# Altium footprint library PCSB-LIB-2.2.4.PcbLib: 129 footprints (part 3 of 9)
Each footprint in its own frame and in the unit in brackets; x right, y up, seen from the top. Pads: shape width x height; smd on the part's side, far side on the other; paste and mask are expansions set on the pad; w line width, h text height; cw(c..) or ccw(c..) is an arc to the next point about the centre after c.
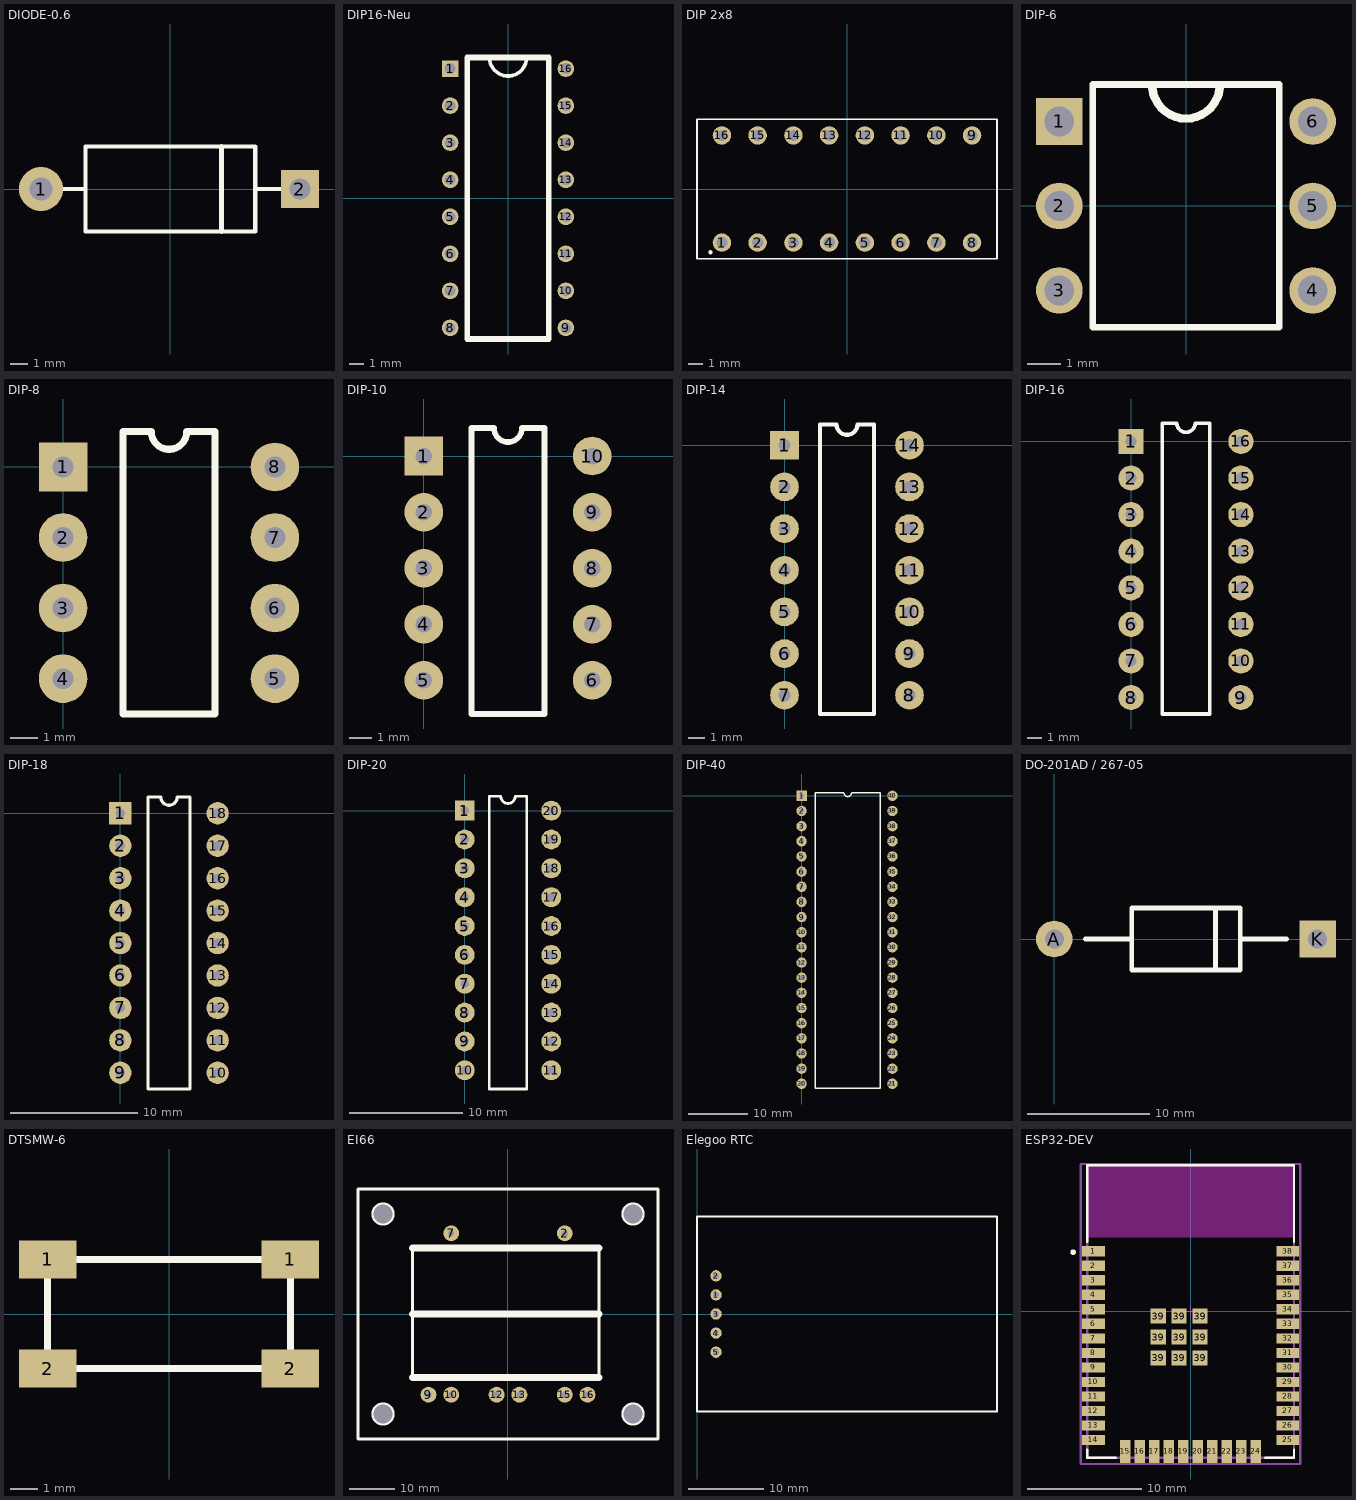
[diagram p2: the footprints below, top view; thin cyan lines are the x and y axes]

## DIODE-0.6 [mm]
pads (2):
  round 2.6 hole 1.35: 1(-7.62,0)
  rect 2.25x2.25 hole 1.25: 2(7.62,0)
Top Overlay:
  lines w0.254: -7,0 -5,0 ; -5,-2.5 -5,2.5 5,2.5 5,-2.5 -4.89,-2.5 ; 5,0 7.016,0
  lines w0.3: 3,-2.5 3,2.5

## DIP16-Neu [mm]
pads (16):
  rect 1.14x1.14 hole 0.74: 1(-3.97,8.89)
  round 1.14 hole 0.74: 2(-3.97,6.35) 3(-3.97,3.81) 4(-3.97,1.27) 5(-3.97,-1.27) 6(-3.97,-3.81) 7(-3.97,-6.35) 8(-3.97,-8.89) 9(3.97,-8.89) 10(3.97,-6.35) 11(3.97,-3.81) 12(3.97,-1.27) 13(3.97,1.27) 14(3.97,3.81) 15(3.97,6.35) 16(3.97,8.89)
Top Overlay:
  lines w0.254: -1.253,9.443 ccw(c0,9.653) 1.27,9.652
  lines w0.4: -2.794,-9.653 -2.794,9.653 2.794,9.653 2.794,-9.653 -2.794,-9.653

## DIP 2x8 [mm]
pads (16):
  round 1.308 hole 0.8: 1(-8.89,-3.81) 2(-6.35,-3.81) 3(-3.81,-3.81) 4(-1.27,-3.81) 5(1.27,-3.81) 6(3.81,-3.81) 7(6.35,-3.81) 8(8.89,-3.81) 9(8.89,3.81) 10(6.35,3.81) 11(3.81,3.81) 12(1.27,3.81) 13(-1.27,3.81) 14(-3.81,3.81) 15(-6.35,3.81) 16(-8.89,3.81)
Top Overlay:
  circle w0.2: c-9.7,-4.5 r0.05
  lines w0.127: -10.66,-4.95 -10.66,4.95 10.66,4.95 10.66,-4.95 -10.66,-4.95

## DIP-6 [mm]
pads (6):
  rect 1.4x1.4 hole 0.9: 1(-3.81,2.54)
  round 1.4 hole 0.9: 2(-3.81,0) 3(-3.81,-2.54) 4(3.81,-2.54) 5(3.81,0) 6(3.81,2.54)
Top Overlay:
  lines w0.2: -2.8,-3.65 2.8,-3.65 2.8,3.65 1.4,3.65 -1.4,3.65 -2.8,3.65 -2.8,-3.65
  lines w0.254: -1.016,3.556 ccw(c0,3.65) 1.016,3.556

## DIP-8 [mm]
pads (8):
  rect 1.75x1.75 hole 0.75: 1(0,0)
  round 1.75 hole 0.75: 2(0,-2.54) 3(0,-5.08) 4(0,-7.62) 5(7.62,-7.62) 6(7.62,-5.08) 7(7.62,-2.54) 8(7.62,0)
Top Overlay:
  lines w0.254: 2.159,-8.89 5.461,-8.89 5.461,1.27 4.445,1.27 cw(c3.81,1.27) 3.175,1.27 2.159,1.27 2.159,-8.89

## DIP-10 [mm]
pads (10):
  rect 1.75x1.75 hole 0.75: 1(0,0)
  round 1.75 hole 0.75: 2(0,-2.54) 3(0,-5.08) 4(0,-7.62) 5(0,-10.16) 6(7.62,-10.16) 7(7.62,-7.62) 8(7.62,-5.08) 9(7.62,-2.54) 10(7.62,0)
Top Overlay:
  lines w0.254: 2.159,-11.684 2.159,1.27 3.175,1.27 ccw(c3.81,1.27) 4.445,1.27 5.461,1.27 5.461,-11.684 2.159,-11.684

## DIP-14 [mm]
pads (14):
  rect 1.75x1.75 hole 0.75: 1(0,0)
  round 1.75 hole 0.75: 2(0,-2.54) 3(0,-5.08) 4(0,-7.62) 5(0,-10.16) 6(0,-12.7) 7(0,-15.24) 8(7.62,-15.24) 9(7.62,-12.7) 10(7.62,-10.16) 11(7.62,-7.62) 12(7.62,-5.08) 13(7.62,-2.54) 14(7.62,0)
Top Overlay:
  lines w0.254: 2.159,-16.383 2.159,1.27 3.175,1.27 ccw(c3.81,1.27) 4.445,1.27 5.461,1.27 5.461,-16.383 2.159,-16.383

## DIP-16 [mm]
pads (16):
  rect 1.75x1.75 hole 0.75: 1(0,0)
  round 1.75 hole 0.75: 2(0,-2.54) 3(0,-5.08) 4(0,-7.62) 5(0,-10.16) 6(0,-12.7) 7(0,-15.24) 8(0,-17.78) 9(7.62,-17.78) 10(7.62,-15.24) 11(7.62,-12.7) 12(7.62,-10.16) 13(7.62,-7.62) 14(7.62,-5.08) 15(7.62,-2.54) 16(7.62,0)
Top Overlay:
  lines w0.254: 2.159,-18.923 5.461,-18.923 5.461,1.27 4.445,1.27 cw(c3.81,1.27) 3.175,1.27 2.159,1.27 2.159,-18.923

## DIP-18 [mm]
pads (18):
  rect 1.75x1.75 hole 0.75: 1(0,0)
  round 1.75 hole 0.75: 2(0,-2.54) 3(0,-5.08) 4(0,-7.62) 5(0,-10.16) 6(0,-12.7) 7(0,-15.24) 8(0,-17.78) 9(0,-20.32) 10(7.62,-20.32) 11(7.62,-17.78) 12(7.62,-15.24) 13(7.62,-12.7) 14(7.62,-10.16) 15(7.62,-7.62) 16(7.62,-5.08) 17(7.62,-2.54) 18(7.62,0)
Top Overlay:
  lines w0.254: 2.159,-21.59 2.159,1.27 3.175,1.27 ccw(c3.81,1.27) 4.445,1.27 5.461,1.27 5.461,-21.59 2.159,-21.59

## DIP-20 [mm]
pads (20):
  rect 1.75x1.75 hole 0.75: 1(0,0)
  round 1.75 hole 0.75: 2(0,-2.54) 3(0,-5.08) 4(0,-7.62) 5(0,-10.16) 6(0,-12.7) 7(0,-15.24) 8(0,-17.78) 9(0,-20.32) 10(0,-22.86) 11(7.62,-22.86) 12(7.62,-20.32) 13(7.62,-17.78) 14(7.62,-15.24) 15(7.62,-12.7) 16(7.62,-10.16) 17(7.62,-7.62) 18(7.62,-5.08) 19(7.62,-2.54) 20(7.62,0)
Top Overlay:
  lines w0.254: 2.159,-24.511 2.159,1.27 3.175,1.27 ccw(c3.81,1.27) 4.445,1.27 5.461,1.27 5.461,-24.511 2.159,-24.511

## DIP-40 [mm]
pads (40):
  rect 1.75x1.75 hole 0.75: 1(0,0)
  round 1.75 hole 0.75: 2(0,-2.54) 3(0,-5.08) 4(0,-7.62) 5(0,-10.16) 6(0,-12.7) 7(0,-15.24) 8(0,-17.78) 9(0,-20.32) 10(0,-22.86) 11(0,-25.4) 12(0,-27.94) 13(0,-30.48) 14(0,-33.02) 15(0,-35.56) 16(0,-38.1) 17(0,-40.64) 18(0,-43.18) 19(0,-45.72) 20(0,-48.26) 21(15.24,-48.26) 22(15.24,-45.72) 23(15.24,-43.18) 24(15.24,-40.64) 25(15.24,-38.1) 26(15.24,-35.56) 27(15.24,-33.02) 28(15.24,-30.48) 29(15.24,-27.94) 30(15.24,-25.4) 31(15.24,-22.86) 32(15.24,-20.32) 33(15.24,-17.78) 34(15.24,-15.24) 35(15.24,-12.7) 36(15.24,-10.16) 37(15.24,-7.62) 38(15.24,-5.08) 39(15.24,-2.54) 40(15.24,0)
Top Overlay:
  lines w0.254: 2.286,-49.022 13.208,-49.022 13.208,0.508 8.382,0.508 cw(c7.747,0.508) 7.112,0.508 2.286,0.508 2.286,-49.022

## DO-201AD / 267-05 [mm]
height 5
pads (2):
  round 3 hole 1.55: A(0,0)
  rect 3x3 hole 1.55: K(21.59,0)
Top Overlay:
  lines w0.4: 2.54,0 6.35,0 ; 13.208,-2.54 13.208,2.54 ; 15.24,0 19.05,0 ; 6.35,-2.54 6.35,2.54 15.24,2.54 15.24,-2.54 6.35,-2.54

## DTSMW-6 [mm]
height 17
pads (4):
  rect 2.1x1.4 smd: 1(-4.45,2) 1(4.45,2) 2(-4.45,-2) 2(4.45,-2)
Top Overlay:
  lines w0.254: -4.45,-2 -4.45,2 4.45,2 4.45,-2 -4.45,-2
3D body: height 17, standoff 0, extent -5.602,-2.802 5.602,2.802

## EI66 [mm]
height 52
pads (12):
  round 0 hole 4.2 unplated: 0(-27.5,-22) 0(-27.5,22) 0(27.5,-22) 0(27.5,22)
  round 3.5 hole 1.35 unplated: 2(12.5,17.75) 7(-12.5,17.75) 9(-17.5,-17.75) 10(-12.5,-17.75) 12(-2.5,-17.75) 13(2.5,-17.75) 15(12.5,-17.75) 16(17.5,-17.75)
Top Overlay:
  circle w0.7: c-27.5,22 r2.2
  circle w0.7: c27.5,22 r2.2
  circle w0.7: c-27.5,-22 r2.2
  circle w0.7: c27.5,-22 r2.2
  lines w0.7: -21,-14 -21,14.5 ; 20,-14 20,14.5 ; -33,-27.5 33,-27.5 33,27.5 -33,27.5 -33,-27.5
  lines w1.5: -21,-14 20,-14 ; -21,0 20,0 ; -21,14.5 20,14.5

## Elegoo RTC [mil]
pads (5):
  round 60 hole 30: 1(100,100) 2(100,200) 3(100,0) 4(100,-100) 5(100,-200)
Top Overlay:
  lines w10: 1574.8,0 1574.8,511.81 ; 1574.8,511.81 0,511.81 0,-511.81 1574.8,-511.81 1574.8,511.81

## ESP32-DEV [mm]
pads (47):
  rect 2x0.9 smd paste+0 mask+0: 1(-8.5,5.26) 2(-8.5,3.99) 3(-8.5,2.72) 4(-8.5,1.45) 5(-8.5,0.18) 6(-8.5,-1.09) 7(-8.5,-2.36) 8(-8.5,-3.63) 9(-8.5,-4.9) 10(-8.5,-6.17) 11(-8.5,-7.44) 12(-8.5,-8.71) 13(-8.5,-9.98) 14(-8.5,-11.25) 25(8.5,-11.25) 26(8.5,-9.98) 27(8.5,-8.71) 28(8.5,-7.44) 29(8.5,-6.17) 30(8.5,-4.9) 31(8.5,-3.63) 32(8.5,-2.36) 33(8.5,-1.09) 34(8.5,0.18) 35(8.5,1.45) 36(8.5,2.72) 37(8.5,3.99) 38(8.5,5.26)
  rect 0.9x2 smd paste+0 mask+0: 15(-5.715,-12.25) 16(-4.445,-12.25) 17(-3.175,-12.25) 18(-1.905,-12.25) 19(-0.635,-12.25) 20(0.635,-12.25) 21(1.905,-12.25) 22(3.175,-12.25) 23(4.445,-12.25) 24(5.715,-12.25)
  rect 1.33x1.33 smd paste+0 mask+0: 39(-2.835,-4.075) 39(-2.835,-2.24) 39(-2.835,-0.405) 39(-1,-4.075) 39(-1,-2.24) 39(-1,-0.405) 39(0.835,-4.075) 39(0.835,-2.24) 39(0.835,-0.405)
Top Overlay:
  circle w0.25: c-10.275,5.185 r0.125
  lines w0.2: -9.05,-12.075 -9.05,-12.8 -6.54,-12.8 ; -9.05,6.085 -9.05,12.8 9.05,12.8 9.05,6.085 ; 6.54,-12.8 9.05,-12.8 9.05,-12.075
Keep-Out Layer:
  rectangle: -9,6.45 9,12.75
  rectangle: -9,6.45 9,12.75
Mechanical 5:
  lines w0.2: -9.6,-13.35 -9.6,12.9 9.6,12.9 9.6,-13.35 -9.6,-13.35
Mechanical 13:
  lines w0.2: -9.05,-12.8 -9.05,12.8 9.05,12.8 9.05,-12.8 -9.05,-12.8
Mechanical 15:
  lines w0.2: -9.6,-13.35 -9.6,12.9 9.6,12.9 9.6,-13.35 -9.6,-13.35
Mechanical 16:
  lines w0.1: -0.5,0 0.5,0 ; 0,-0.5 0,0.5
3D body "UNK_Espressif_Systems_ESP32-WROOM-32D_eec.STEP": height 0.25, standoff 0, extent -9.6,-13.35 9.6,12.9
